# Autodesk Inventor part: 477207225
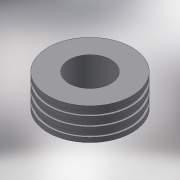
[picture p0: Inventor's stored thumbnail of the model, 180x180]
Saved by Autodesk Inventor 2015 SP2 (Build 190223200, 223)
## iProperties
Created: 2017-08
Part Number: 477207225
Material: Generic
Description: PLASSON MAN HOLE ADAPTOR 225
Document SubType Name: Modeling
Designer: Кирилл
Density: 1 g/cm^3
Appearance: Default
Author: Кирилл
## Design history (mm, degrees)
derived "37020-477207.ipt"
feature "Solid1::37020-477207.ipt"
tag "TaggingFeature1"
body "Solid1"
other parameters: "d0" = 135, "d1" = 355, "d2" = 337.25, "d3" = 198, "d4" = 225, "d6" = 44, "L_" = 135, "d_" = 225, "d_1" = 198, "D_" = 355, "H_" = 44
